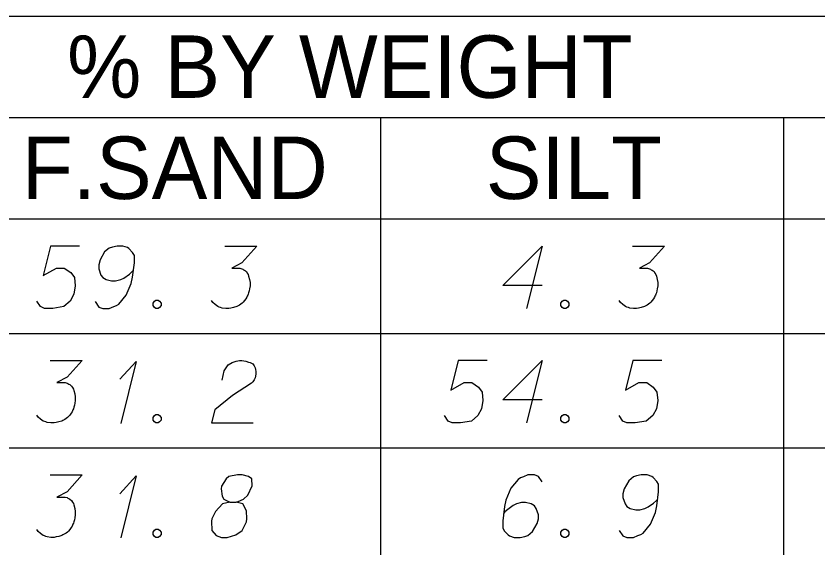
# Model space of a CAD drawing. Extents: x 2074207 to 2076812, y 516372 to 523312.
# Drawn here: x 2076560.1 to 2076621.8, y 517338.3 to 517379.2 of the extents above; entities that cross this region are included whole.
import ezdxf

# ---------------------------------------------------------------- set-up
doc = ezdxf.new("R2010")
doc.units = 0
for name, color, linetype in [('Prop DirtTable_ Soil Test Results - Outline (Major)', 7, 'Continuous'), ('Prop DirtTable_ Soil Test Results - Outline (Minor)', 7, 'Continuous'), ('Prop DirtTable_ Soil Test Results - Tx (Header - Small)', 7, 'Continuous'), ('Prop DirtTable_ Soil Test Results - Tx (Sample Data)', 7, 'Continuous')]:
    doc.layers.add(name, color=color, linetype=linetype)

msp = doc.modelspace()

# ---------------------------------------------------------------- linework, layer by layer
at = {"layer": 'Prop DirtTable_ Soil Test Results - Outline (Major)'}
msp.add_line((2076260.609, 517363.585), (2076811.903, 517363.585), dxfattribs=at)
msp.add_line((2076260.609, 517363.585), (2076811.903, 517363.585), dxfattribs=at)
at = {"layer": 'Prop DirtTable_ Soil Test Results - Outline (Minor)'}
for p, q in [((2076260.609, 517379.185), (2076811.903, 517379.185)), ((2076526.074, 517371.385), (2076731.93, 517371.385)), ((2076588.114, 517371.385), (2076588.114, 517354.785)), ((2076619.134, 517354.785), (2076619.134, 517371.385)), ((2076260.609, 517354.785), (2076811.903, 517354.785)), ((2076260.609, 517354.785), (2076811.903, 517354.785)), ((2076588.114, 517354.785), (2076588.114, 517345.985)), ((2076619.134, 517345.985), (2076619.134, 517354.785)), ((2076260.609, 517345.985), (2076811.903, 517345.985)), ((2076260.609, 517345.985), (2076811.903, 517345.985)), ((2076588.114, 517345.985), (2076588.114, 517337.185)), ((2076619.134, 517337.185), (2076619.134, 517345.985))]:
    msp.add_line(p, q, dxfattribs=at)
at = {"layer": 'Prop DirtTable_ Soil Test Results - Tx (Sample Data)'}
for points in [[(2076564.956, 517361.498), (2076562.734, 517361.498), (2076562.169, 517359.23), (2076563.192, 517359.797), (2076563.792, 517359.797), (2076564.286, 517359.457), (2076564.568, 517359.079), (2076564.639, 517358.437), (2076564.533, 517357.794), (2076564.251, 517357.265), (2076563.757, 517356.849), (2076562.91, 517356.698), (2076562.275, 517356.698), (2076561.958, 517356.849), (2076561.676, 517357.265)], [(2076566.156, 517357.227), (2076566.438, 517356.811), (2076566.755, 517356.698), (2076567.249, 517356.698), (2076567.602, 517356.849), (2076567.814, 517356.925), (2076567.99, 517357.038), (2076568.554, 517357.718), (2076568.942, 517358.626), (2076569.048, 517359.117), (2076569.189, 517360.213), (2076569.189, 517360.78), (2076569.048, 517361.007), (2076568.766, 517361.309), (2076568.66, 517361.385), (2076568.307, 517361.498), (2076567.849, 517361.498), (2076567.496, 517361.422), (2076567.249, 517361.347), (2076566.896, 517361.044), (2076566.544, 517360.44), (2076566.438, 517360.062), (2076566.438, 517359.759), (2076566.614, 517359.268), (2076566.755, 517359.079), (2076567.002, 517358.928), (2076567.426, 517358.815), (2076567.743, 517358.815), (2076568.131, 517358.928), (2076568.378, 517359.041), (2076568.801, 517359.344), (2076569.013, 517359.533), (2076569.119, 517359.646)], [(2076576.139, 517361.498), (2076578.608, 517361.498), (2076577.444, 517360.213), (2076576.668, 517359.797), (2076577.303, 517359.797), (2076577.444, 517359.759), (2076577.514, 517359.722), (2076577.585, 517359.684), (2076577.655, 517359.646), (2076577.797, 517359.533), (2076577.867, 517359.419), (2076577.938, 517359.306), (2076577.973, 517359.192), (2076578.043, 517358.928), (2076578.079, 517358.701), (2076578.079, 517358.588), (2076578.079, 517358.437), (2076578.043, 517358.21), (2076578.008, 517358.059), (2076577.973, 517357.907), (2076577.938, 517357.794), (2076577.902, 517357.718), (2076577.867, 517357.643), (2076577.832, 517357.567), (2076577.761, 517357.454), (2076577.655, 517357.303), (2076577.55, 517357.189), (2076577.479, 517357.114), (2076577.373, 517357.038), (2076577.267, 517356.963), (2076577.126, 517356.887), (2076577.056, 517356.849), (2076576.809, 517356.774), (2076576.597, 517356.736), (2076576.456, 517356.698), (2076576.209, 517356.698), (2076575.927, 517356.736), (2076575.821, 517356.774), (2076575.715, 517356.811), (2076575.609, 517356.849), (2076575.504, 517356.925), (2076575.398, 517357), (2076575.221, 517357.152), (2076575.116, 517357.303)], [(2076600.549, 517358.474), (2076597.516, 517358.474), (2076600.549, 517361.498), (2076599.35, 517356.698)], [(2076607.499, 517361.498), (2076609.968, 517361.498), (2076608.804, 517360.213), (2076608.028, 517359.797), (2076608.663, 517359.797), (2076608.804, 517359.759), (2076608.874, 517359.722), (2076608.945, 517359.684), (2076609.015, 517359.646), (2076609.157, 517359.533), (2076609.227, 517359.419), (2076609.298, 517359.306), (2076609.333, 517359.192), (2076609.403, 517358.928), (2076609.439, 517358.701), (2076609.439, 517358.588), (2076609.439, 517358.437), (2076609.403, 517358.21), (2076609.368, 517358.059), (2076609.333, 517357.907), (2076609.298, 517357.794), (2076609.262, 517357.718), (2076609.227, 517357.643), (2076609.192, 517357.567), (2076609.121, 517357.454), (2076609.015, 517357.303), (2076608.91, 517357.189), (2076608.839, 517357.114), (2076608.733, 517357.038), (2076608.627, 517356.963), (2076608.486, 517356.887), (2076608.416, 517356.849), (2076608.169, 517356.774), (2076607.957, 517356.736), (2076607.816, 517356.698), (2076607.569, 517356.698), (2076607.287, 517356.736), (2076607.181, 517356.774), (2076607.075, 517356.811), (2076606.969, 517356.849), (2076606.864, 517356.925), (2076606.758, 517357), (2076606.581, 517357.152), (2076606.476, 517357.303)], [(2076570.847, 517357.341), (2076571.024, 517357.341), (2076571.129, 517357.265), (2076571.235, 517357.114), (2076571.235, 517356.925), (2076571.129, 517356.774), (2076571.024, 517356.698), (2076570.847, 517356.698), (2076570.741, 517356.774), (2076570.636, 517356.925), (2076570.636, 517357.114), (2076570.741, 517357.265), (2076570.847, 517357.341)], [(2076602.207, 517357.341), (2076602.384, 517357.341), (2076602.489, 517357.265), (2076602.595, 517357.114), (2076602.595, 517356.925), (2076602.489, 517356.774), (2076602.384, 517356.698), (2076602.207, 517356.698), (2076602.101, 517356.774), (2076601.996, 517356.925), (2076601.996, 517357.114), (2076602.101, 517357.265), (2076602.207, 517357.341)], [(2076562.699, 517352.698), (2076565.168, 517352.698), (2076564.004, 517351.413), (2076563.228, 517350.997), (2076563.863, 517350.997), (2076564.004, 517350.959), (2076564.074, 517350.922), (2076564.145, 517350.884), (2076564.215, 517350.846), (2076564.357, 517350.733), (2076564.427, 517350.619), (2076564.498, 517350.506), (2076564.533, 517350.392), (2076564.603, 517350.128), (2076564.639, 517349.901), (2076564.639, 517349.788), (2076564.639, 517349.637), (2076564.603, 517349.41), (2076564.568, 517349.259), (2076564.533, 517349.107), (2076564.498, 517348.994), (2076564.462, 517348.918), (2076564.427, 517348.843), (2076564.392, 517348.767), (2076564.321, 517348.654), (2076564.215, 517348.503), (2076564.11, 517348.389), (2076564.039, 517348.314), (2076563.933, 517348.238), (2076563.827, 517348.163), (2076563.686, 517348.087), (2076563.616, 517348.049), (2076563.369, 517347.974), (2076563.157, 517347.936), (2076563.016, 517347.898), (2076562.769, 517347.898), (2076562.487, 517347.936), (2076562.381, 517347.974), (2076562.275, 517348.011), (2076562.169, 517348.049), (2076562.064, 517348.125), (2076561.958, 517348.2), (2076561.781, 517348.352), (2076561.676, 517348.503)], [(2076568.06, 517351.262), (2076569.33, 517352.622), (2076568.131, 517347.86)], [(2076575.927, 517351.186), (2076576.103, 517351.904), (2076576.386, 517352.358), (2076576.703, 517352.547), (2076577.02, 517352.66), (2076577.267, 517352.698), (2076577.444, 517352.698), (2076577.761, 517352.66), (2076577.973, 517352.585), (2076578.079, 517352.547), (2076578.29, 517352.433), (2076578.396, 517352.282), (2076578.467, 517352.131), (2076578.502, 517352.018), (2076578.537, 517351.867), (2076578.537, 517351.678), (2076578.502, 517351.489), (2076578.467, 517351.375), (2076578.396, 517351.224), (2076578.29, 517351.073), (2076578.185, 517350.959), (2076576.738, 517350.015), (2076575.363, 517348.918), (2076575.116, 517347.898), (2076578.326, 517347.898)], [(2076596.316, 517352.698), (2076594.094, 517352.698), (2076593.529, 517350.43), (2076594.552, 517350.997), (2076595.152, 517350.997), (2076595.646, 517350.657), (2076595.928, 517350.279), (2076595.999, 517349.637), (2076595.893, 517348.994), (2076595.611, 517348.465), (2076595.117, 517348.049), (2076594.27, 517347.898), (2076593.635, 517347.898), (2076593.318, 517348.049), (2076593.036, 517348.465)], [(2076600.549, 517349.674), (2076597.516, 517349.674), (2076600.549, 517352.698), (2076599.35, 517347.898)], [(2076609.756, 517352.698), (2076607.534, 517352.698), (2076606.969, 517350.43), (2076607.992, 517350.997), (2076608.592, 517350.997), (2076609.086, 517350.657), (2076609.368, 517350.279), (2076609.439, 517349.637), (2076609.333, 517348.994), (2076609.051, 517348.465), (2076608.557, 517348.049), (2076607.71, 517347.898), (2076607.075, 517347.898), (2076606.758, 517348.049), (2076606.476, 517348.465)], [(2076570.847, 517348.541), (2076571.024, 517348.541), (2076571.129, 517348.465), (2076571.235, 517348.314), (2076571.235, 517348.125), (2076571.129, 517347.974), (2076571.024, 517347.898), (2076570.847, 517347.898), (2076570.741, 517347.974), (2076570.636, 517348.125), (2076570.636, 517348.314), (2076570.741, 517348.465), (2076570.847, 517348.541)], [(2076602.207, 517348.541), (2076602.384, 517348.541), (2076602.489, 517348.465), (2076602.595, 517348.314), (2076602.595, 517348.125), (2076602.489, 517347.974), (2076602.384, 517347.898), (2076602.207, 517347.898), (2076602.101, 517347.974), (2076601.996, 517348.125), (2076601.996, 517348.314), (2076602.101, 517348.465), (2076602.207, 517348.541)], [(2076562.699, 517343.898), (2076565.168, 517343.898), (2076564.004, 517342.613), (2076563.228, 517342.197), (2076563.863, 517342.197), (2076564.004, 517342.159), (2076564.074, 517342.122), (2076564.145, 517342.084), (2076564.215, 517342.046), (2076564.357, 517341.933), (2076564.427, 517341.819), (2076564.498, 517341.706), (2076564.533, 517341.592), (2076564.603, 517341.328), (2076564.639, 517341.101), (2076564.639, 517340.988), (2076564.639, 517340.837), (2076564.603, 517340.61), (2076564.568, 517340.459), (2076564.533, 517340.307), (2076564.498, 517340.194), (2076564.462, 517340.118), (2076564.427, 517340.043), (2076564.392, 517339.967), (2076564.321, 517339.854), (2076564.215, 517339.703), (2076564.11, 517339.589), (2076564.039, 517339.514), (2076563.933, 517339.438), (2076563.827, 517339.363), (2076563.686, 517339.287), (2076563.616, 517339.249), (2076563.369, 517339.174), (2076563.157, 517339.136), (2076563.016, 517339.098), (2076562.769, 517339.098), (2076562.487, 517339.136), (2076562.381, 517339.174), (2076562.275, 517339.211), (2076562.169, 517339.249), (2076562.064, 517339.325), (2076561.958, 517339.4), (2076561.781, 517339.552), (2076561.676, 517339.703)], [(2076568.06, 517342.462), (2076569.33, 517343.822), (2076568.131, 517339.06)], [(2076576.527, 517341.819), (2076577.02, 517341.819), (2076577.162, 517341.857), (2076577.585, 517342.046), (2076577.902, 517342.348), (2076578.255, 517343.067), (2076578.22, 517343.596), (2076577.973, 517343.785), (2076577.479, 517343.898), (2076577.126, 517343.898), (2076576.456, 517343.785), (2076576.244, 517343.596), (2076575.892, 517343.029), (2076575.856, 517342.84), (2076575.927, 517342.273), (2076576.068, 517342.046), (2076576.527, 517341.819), (2076575.962, 517341.668), (2076575.433, 517341.101), (2076575.151, 517340.534), (2076575.116, 517340.345), (2076575.151, 517339.627), (2076575.468, 517339.249), (2076575.892, 517339.098), (2076576.315, 517339.098), (2076576.985, 517339.287), (2076577.479, 517339.627), (2076577.797, 517340.307), (2076577.832, 517340.534), (2076577.797, 517341.139), (2076577.514, 517341.668), (2076577.02, 517341.819)], [(2076600.549, 517343.369), (2076600.267, 517343.785), (2076599.95, 517343.898), (2076599.456, 517343.898), (2076599.103, 517343.747), (2076598.891, 517343.671), (2076598.715, 517343.558), (2076598.151, 517342.878), (2076597.763, 517341.97), (2076597.657, 517341.479), (2076597.516, 517340.383), (2076597.516, 517339.816), (2076597.657, 517339.589), (2076597.939, 517339.287), (2076598.045, 517339.211), (2076598.398, 517339.098), (2076598.856, 517339.098), (2076599.209, 517339.174), (2076599.456, 517339.249), (2076599.809, 517339.552), (2076600.161, 517340.156), (2076600.267, 517340.534), (2076600.267, 517340.837), (2076600.091, 517341.328), (2076599.95, 517341.517), (2076599.703, 517341.668), (2076599.279, 517341.781), (2076598.962, 517341.781), (2076598.574, 517341.668), (2076598.327, 517341.555), (2076597.904, 517341.252), (2076597.692, 517341.063), (2076597.586, 517340.95)], [(2076606.476, 517339.627), (2076606.758, 517339.211), (2076607.075, 517339.098), (2076607.569, 517339.098), (2076607.922, 517339.249), (2076608.134, 517339.325), (2076608.31, 517339.438), (2076608.874, 517340.118), (2076609.262, 517341.026), (2076609.368, 517341.517), (2076609.509, 517342.613), (2076609.509, 517343.18), (2076609.368, 517343.407), (2076609.086, 517343.709), (2076608.98, 517343.785), (2076608.627, 517343.898), (2076608.169, 517343.898), (2076607.816, 517343.822), (2076607.569, 517343.747), (2076607.216, 517343.444), (2076606.864, 517342.84), (2076606.758, 517342.462), (2076606.758, 517342.159), (2076606.934, 517341.668), (2076607.075, 517341.479), (2076607.322, 517341.328), (2076607.746, 517341.215), (2076608.063, 517341.215), (2076608.451, 517341.328), (2076608.698, 517341.441), (2076609.121, 517341.744), (2076609.333, 517341.933), (2076609.439, 517342.046)], [(2076570.847, 517339.741), (2076571.024, 517339.741), (2076571.129, 517339.665), (2076571.235, 517339.514), (2076571.235, 517339.325), (2076571.129, 517339.174), (2076571.024, 517339.098), (2076570.847, 517339.098), (2076570.741, 517339.174), (2076570.636, 517339.325), (2076570.636, 517339.514), (2076570.741, 517339.665), (2076570.847, 517339.741)], [(2076602.207, 517339.741), (2076602.384, 517339.741), (2076602.489, 517339.665), (2076602.595, 517339.514), (2076602.595, 517339.325), (2076602.489, 517339.174), (2076602.384, 517339.098), (2076602.207, 517339.098), (2076602.101, 517339.174), (2076601.996, 517339.325), (2076601.996, 517339.514), (2076602.101, 517339.665), (2076602.207, 517339.741)]]:
    msp.add_lwpolyline(points, dxfattribs=at)

# ---------------------------------------------------------------- texts
at = {"layer": 'Prop DirtTable_ Soil Test Results - Tx (Header - Small)'}
for s, height, p in [('% BY WEIGHT', 4.79998, (2076564.009, 517372.896)), ('F.SAND', 4.8, (2076560.529, 517365.121)), ('SILT', 4.8, (2076596.215, 517365.121))]:
    msp.add_text(s, height=height, dxfattribs=at).set_placement(p)

doc.saveas('drawing.dxf')
